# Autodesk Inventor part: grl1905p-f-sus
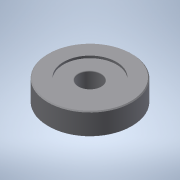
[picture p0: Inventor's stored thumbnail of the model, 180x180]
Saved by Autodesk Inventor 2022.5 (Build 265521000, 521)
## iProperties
Created: 2016-12
Part Number: grl1905p-f-sus
Material: 一般
Document SubType Name: Modeling
Designer: imaocorp
Density: 1 g/cm^3
Appearance: 既定
Author: imaocorp
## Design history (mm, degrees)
node "grl1905p-f-sus.x_t1"
node "grl1905p-f-sus"
node "Base1"
